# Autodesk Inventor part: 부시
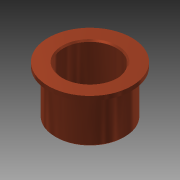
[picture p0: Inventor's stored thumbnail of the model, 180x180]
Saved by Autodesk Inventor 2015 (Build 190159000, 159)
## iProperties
Created: 2015-10
Part Number: 부시
Document SubType Name: Modeling
Designer: mdu
Density: 7.86 g/cm^3
Material: Steel, Mild
Mass: 246.97 g
Surface Area: 129.264 cm^2
Volume: 31.4212 cm^3
Appearance: Copper - Satin
Author: mdu
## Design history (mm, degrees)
sketch "스케치1"
  geometry: C1 r 31 at (0, 0) reference; C2 r 25 at (0, 0) reference; C3 r 30 at (0, 0) reference; 1 further point
  node "참조1"
  node "참조2"
  node "참조4"
extrude "돌출1" new body sketch "스케치1" distance "d0" = 3; taper "d1" = 0 deg
extrude "돌출2" join sketch "스케치1" distance "d2" = 35; taper "d3" = 0 deg
chamfer "모따기1" distance "d6" = 1; stored, may be unused: second distance "d7" = 2, angle "d8" = 45 deg
sketch "스케치3"
  geometry: C1 r 19 at (0, 0); 1 further point
  constraints: 1 centre point, 1 coincident
  dimensions: "d13" = 38 diameter of C1
extrude "돌출4" cut sketch "스케치3" stored distance "d14" = 10; taper "d15" = 0 deg
chamfer "모따기3" distance "d16" = 1; stored, may be unused: second distance "d17" = 2, angle "d18" = 45 deg
node "솔리드1"
